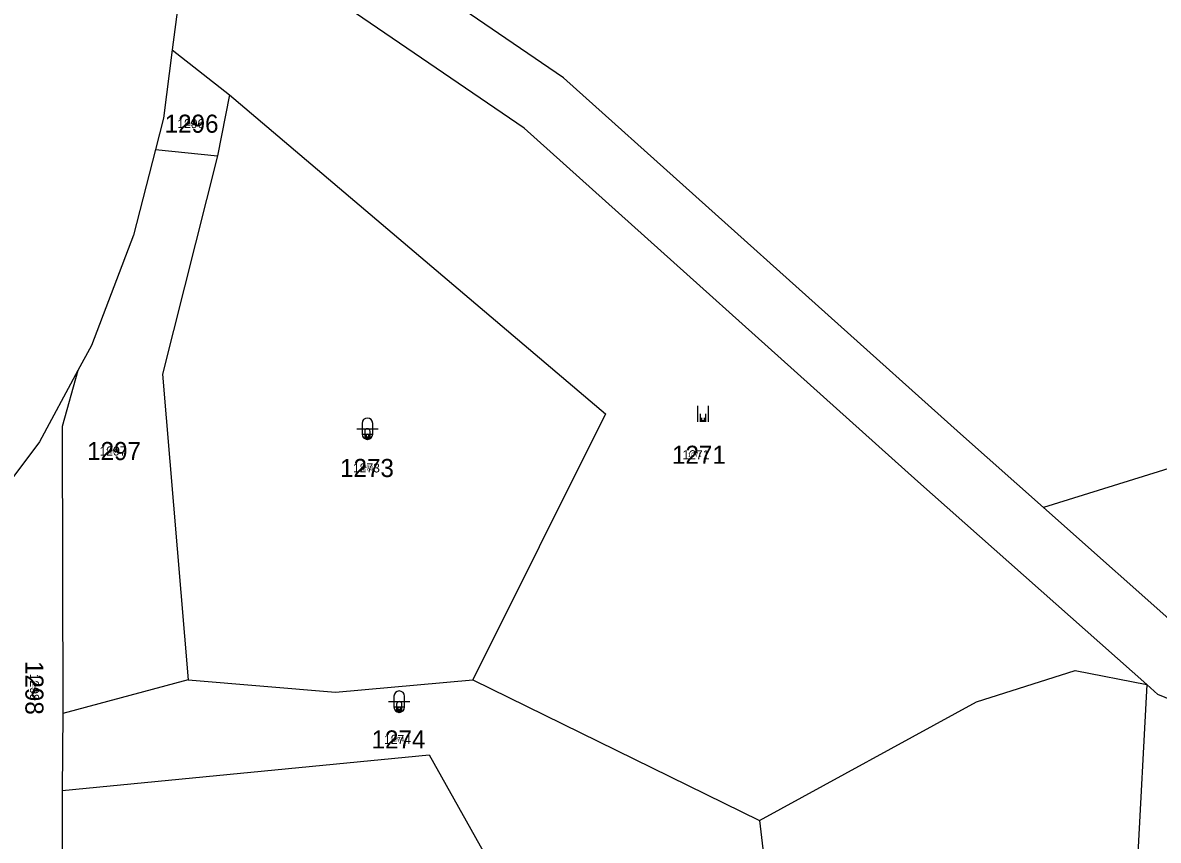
# Model space of a CAD drawing. Extents: x -744652 to -739090, y -980828 to -975855.
# Drawn here: x -741321.4 to -741214.8, y -978878.4 to -978801.7 of the extents above; entities that cross this region are included whole.
import ezdxf

# ---------------------------------------------------------------- set-up
doc = ezdxf.new("R2010")
doc.units = 0
for name, color, linetype in [('KAT_02_hranice parcel', 7, 'Continuous'), ('KAT_03_1000_čísla parcelní', 7, 'Continuous'), ('KAT_03_100_čísla parcelní', 7, 'Continuous'), ('KAT_03_250_čísla parcelní', 7, 'Continuous'), ('KAT_03_500_čísla parcelní', 7, 'Continuous'), ('KAT_05_1000_značky kultur', 7, 'Continuous'), ('KAT_05_100_značky kultur', 7, 'Continuous'), ('KAT_05_250_značky kultur', 7, 'Continuous'), ('KAT_05_500_značky kultur', 7, 'Continuous')]:
    doc.layers.add(name, color=color, linetype=linetype)

msp = doc.modelspace()

# ---------------------------------------------------------------- linework, layer by layer
at = {"layer": 'KAT_02_hranice parcel'}
for p, q in [((-741307.38, -978804.21), (-741302, -978808.43)), ((-741302, -978808.43), (-741303.14, -978814.16)), ((-741308.96, -978813.56), (-741303.14, -978814.16)), ((-741305.9, -978863.36), (-741317.67, -978866.53)), ((-741279.17, -978863.36), (-741252.23, -978876.59)), ((-741215.88, -978863.81), (-741217.95, -978902.92)), ((-741317.67, -978866.53), (-741317.71, -978873.77)), ((-741252.23, -978876.59), (-741251.68, -978881.25))]:
    msp.add_line(p, q, dxfattribs=at)
for points in [[(-741042.01, -978354.8), (-741059.45, -978390.12), (-741080.93, -978447.61), (-741103.79, -978505.52), (-741111.84, -978540.89), (-741127.54, -978581), (-741128.61, -978588.84), (-741124.02, -978602), (-741143.08, -978723.08), (-741149.44, -978773.77), (-741163.61, -978818.61), (-741171.5, -978836.18), (-741177.61, -978843.14), (-741209.17, -978842.1), (-741225.58, -978847.19)], [(-741225.58, -978847.19), (-741233.37, -978840.28), (-741270.64, -978806.84), (-741303.64, -978784.32)], [(-741307.39, -978789.02), (-741306.18, -978794.88), (-741307.38, -978804.21)], [(-741215.88, -978863.81), (-741237.37, -978844.76), (-741274.34, -978811.58), (-741307.39, -978789.02)], [(-741307.38, -978804.21), (-741308.2, -978810.62), (-741308.96, -978813.56)], [(-741302, -978808.43), (-741266.71, -978838.4), (-741279.17, -978863.36)], [(-741308.96, -978813.56), (-741311.04, -978821.63), (-741314.98, -978831.99), (-741316.24, -978834.32)], [(-741303.14, -978814.16), (-741308.29, -978834.68), (-741305.9, -978863.36)], [(-741316.24, -978834.32), (-741319.86, -978841.04), (-741326.2, -978849.48)], [(-741316.24, -978834.32), (-741317.71, -978839.58), (-741317.67, -978866.53)], [(-741225.58, -978847.19), (-741211.83, -978859.39), (-741177.82, -978869.87)], [(-741305.9, -978863.36), (-741292.06, -978864.54), (-741279.17, -978863.36)], [(-741252.23, -978876.59), (-741231.85, -978865.44), (-741222.59, -978862.5), (-741215.88, -978863.81)], [(-741087.49, -978941.92), (-741092.84, -978928.41), (-741105.82, -978916.92), (-741123.33, -978906.92), (-741149.15, -978893.09), (-741159.63, -978887.39), (-741214.83, -978864.75), (-741215.88, -978863.81)], [(-741317.71, -978873.77), (-741283.27, -978870.42), (-741271.51, -978891.35)], [(-741317.71, -978873.77), (-741317.71, -978882.38), (-741316.7, -978888.06)]]:
    msp.add_lwpolyline(points, dxfattribs=at)
at = {"layer": 'KAT_05_1000_značky kultur'}
for p, q in [((-741258.03, -978839.15), (-741258.03, -978837.65)), ((-741257.03, -978839.15), (-741257.03, -978837.65)), ((-741290.06, -978839.79), (-741288.06, -978839.79)), ((-741289.56, -978839.29), (-741289.56, -978840.29)), ((-741288.56, -978840.29), (-741288.56, -978839.29)), ((-741287.07, -978865.42), (-741285.07, -978865.42)), ((-741286.57, -978864.92), (-741286.57, -978865.92)), ((-741285.57, -978865.92), (-741285.57, -978864.92))]:
    msp.add_line(p, q, dxfattribs=at)
for centre, start, end in [((-741289.06, -978839.29), 0, 180), ((-741289.06, -978840.29), 180, 359.9879), ((-741286.07, -978864.92), 0, 180), ((-741286.07, -978865.92), 180, 359.9879)]:
    msp.add_arc(centre, 0.5, start, end, dxfattribs=at)
at = {"layer": 'KAT_05_100_značky kultur'}
for p, q in [((-741257.57, -978839.15), (-741257.57, -978839)), ((-741257.47, -978839.15), (-741257.47, -978839)), ((-741289.16, -978840.69), (-741288.96, -978840.69)), ((-741289.11, -978840.64), (-741289.11, -978840.74)), ((-741289.01, -978840.74), (-741289.01, -978840.64)), ((-741286.17, -978866.32), (-741285.97, -978866.32)), ((-741286.12, -978866.27), (-741286.12, -978866.37)), ((-741286.02, -978866.37), (-741286.02, -978866.27))]:
    msp.add_line(p, q, dxfattribs=at)
for centre, start, end in [((-741289.06, -978840.64), 0, 180), ((-741289.06, -978840.74), 180, 359.9879), ((-741286.07, -978866.27), 0, 180), ((-741286.07, -978866.37), 180, 359.9879)]:
    msp.add_arc(centre, 0.05, start, end, dxfattribs=at)
at = {"layer": 'KAT_05_250_značky kultur'}
for p, q in [((-741257.65, -978839.15), (-741257.65, -978838.78)), ((-741257.4, -978839.15), (-741257.4, -978838.78)), ((-741289.31, -978840.54), (-741288.81, -978840.54)), ((-741289.19, -978840.42), (-741289.19, -978840.67)), ((-741288.93, -978840.67), (-741288.93, -978840.42)), ((-741286.32, -978866.17), (-741285.82, -978866.17)), ((-741286.2, -978866.05), (-741286.2, -978866.3)), ((-741285.94, -978866.3), (-741285.94, -978866.05))]:
    msp.add_line(p, q, dxfattribs=at)
for centre, start, end in [((-741289.06, -978840.42), 0, 180), ((-741289.06, -978840.67), 180, 359.9879), ((-741286.07, -978866.05), 0, 180), ((-741286.07, -978866.3), 180, 359.9879)]:
    msp.add_arc(centre, 0.125, start, end, dxfattribs=at)
at = {"layer": 'KAT_05_500_značky kultur'}
for p, q in [((-741257.78, -978839.15), (-741257.78, -978838.4)), ((-741257.28, -978839.15), (-741257.28, -978838.4)), ((-741289.56, -978840.29), (-741288.56, -978840.29)), ((-741289.31, -978840.04), (-741289.31, -978840.54)), ((-741288.81, -978840.54), (-741288.81, -978840.04)), ((-741286.57, -978865.92), (-741285.57, -978865.92)), ((-741286.32, -978865.67), (-741286.32, -978866.17)), ((-741285.82, -978866.17), (-741285.82, -978865.67))]:
    msp.add_line(p, q, dxfattribs=at)
for centre, start, end in [((-741289.06, -978840.04), 0, 180), ((-741289.06, -978840.54), 180, 359.9879), ((-741286.07, -978865.67), 0, 180), ((-741286.07, -978866.17), 180, 359.9879)]:
    msp.add_arc(centre, 0.25, start, end, dxfattribs=at)

# ---------------------------------------------------------------- texts
at = {"layer": 'KAT_03_1000_čísla parcelní'}
for s, p in [('1296', (-741308.1, -978812)), ('1297', (-741315.38, -978842.74)), ('1271', (-741260.46, -978843.09)), ('1273', (-741291.63, -978844.33)), ('1274', (-741288.67, -978869.82))]:
    msp.add_text(s, height=1.7, dxfattribs=at).set_placement(p)
msp.add_text('1298', height=1.7, rotation=270, dxfattribs=at).set_placement((-741321.18, -978861.6))
at = {"layer": 'KAT_03_100_čísla parcelní'}
for s, p in [('1296', (-741305.96, -978811.23)), ('1297', (-741313.28, -978841.97)), ('1271', (-741258.67, -978842.32)), ('1273', (-741289.45, -978843.56)), ('1274', (-741286.57, -978869.05))]:
    msp.add_text(s, height=0.17, dxfattribs=at).set_placement(p)
msp.add_text('1298', height=0.17, rotation=270, dxfattribs=at).set_placement((-741320.41, -978863.75))
at = {"layer": 'KAT_03_250_čísla parcelní'}
for s, p in [('1296', (-741306.32, -978811.36)), ('1297', (-741313.63, -978842.1)), ('1271', (-741258.97, -978842.45)), ('1273', (-741289.82, -978843.69)), ('1274', (-741286.92, -978869.18))]:
    msp.add_text(s, height=0.425, dxfattribs=at).set_placement(p)
msp.add_text('1298', height=0.425, rotation=270, dxfattribs=at).set_placement((-741320.54, -978863.39))
at = {"layer": 'KAT_03_500_čísla parcelní'}
for s, p in [('1296', (-741306.91, -978811.57)), ('1297', (-741314.21, -978842.31)), ('1271', (-741259.47, -978842.66)), ('1273', (-741290.42, -978843.9)), ('1274', (-741287.5, -978869.39))]:
    msp.add_text(s, height=0.85, dxfattribs=at).set_placement(p)
msp.add_text('1298', height=0.85, rotation=270, dxfattribs=at).set_placement((-741320.75, -978862.8))

doc.saveas('drawing.dxf')
